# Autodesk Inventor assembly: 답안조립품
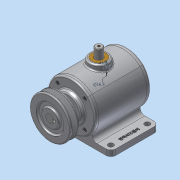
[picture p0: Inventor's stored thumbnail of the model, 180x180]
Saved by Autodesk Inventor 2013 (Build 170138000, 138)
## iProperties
Created: 2015-08
Part Number: 답안조립품
Document SubType Name: Assembly
Designer: Administrator
Mass: 2990.33 g
Surface Area: 2017.36 cm^2
Volume: 938.374 cm^3
Density: 3.18671 g/cm^3
Author: Administrator
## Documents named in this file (14)
- C:\Users\Administrator\Desktop\350806V1017-1\답안조립품.iam
- C:\Users\Administrator\Desktop\350806V1017-1\본체.ipt
- C:\Users\Administrator\Desktop\350806V1017-1\앞커버.ipt
- C:\Users\Administrator\Desktop\350806V1017-1\베어링 6203.ipt
- C:\Users\Administrator\Desktop\350806V1017-1\오일실.ipt
- C:\Users\Administrator\Desktop\350806V1017-1\M4-소켓머리.ipt
- C:\Users\Administrator\Desktop\350806V1017-1\뒷커버.ipt
- C:\Users\Administrator\Desktop\350806V1017-1\부시.ipt
- C:\Users\Administrator\Desktop\350806V1017-1\축.ipt
- C:\Users\Administrator\Desktop\350806V1017-1\슬라이더.ipt
- C:\Users\Administrator\Desktop\350806V1017-1\스프링1 [가변부품].ipt
- C:\Users\Administrator\Desktop\350806V1017-1\KS B 1311 - 5 x 5 x 18I.ipt
- C:\Users\Administrator\Desktop\350806V1017-1\V-벨트풀리.ipt
- C:\Users\Administrator\Desktop\350806V1017-1\KS B 1028  - 납작점M4x5.ipt
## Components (14 placed, 6 different names)
1. 7-베어링 6203:1
2. 8-오일실:1
3. 7-베어링 6203:2
4. KS B 1311 (I) 5 x 5 x 18:1 — 각도:2, 각도:3
5. V-벨트풀리:1 — 각도:3
6. KS B 1028 납작점 - 미터 납작점M4x5:1
7. 9-M4-소켓머리:1
8. 9-M4-소켓머리:2
9. 9-M4-소켓머리:3
10. 9-M4-소켓머리:4
11. 9-M4-소켓머리:5
12. 9-M4-소켓머리:6
13. 9-M4-소켓머리:7
14. 9-M4-소켓머리:8
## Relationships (2: Angle 2)
- 각도:2 [Angle]: KS B 1311 (I) 5 x 5 x 18:1
- 각도:3 [Angle]: KS B 1311 (I) 5 x 5 x 18:1 ↔ V-벨트풀리:1
